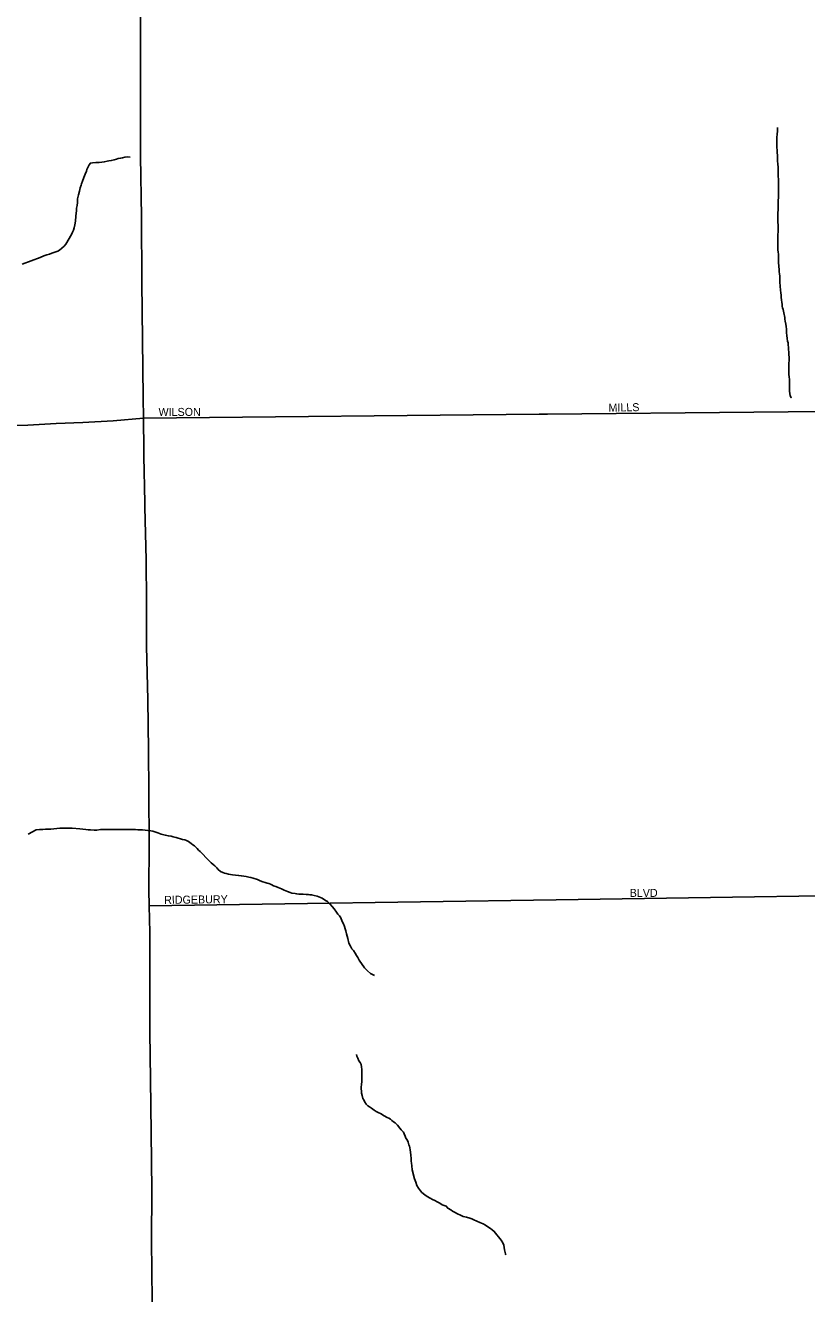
# Model space of a CAD drawing. Extents: x 2139079 to 2262683, y 1235796 to 1334992.
# Drawn here: x 2242458 to 2247339, y 1285350 to 1293274 of the extents above; entities that cross this region are included whole.
import ezdxf

# ---------------------------------------------------------------- set-up
doc = ezdxf.new("R2010")
doc.units = 0
for name, color, linetype in [('GM_X_City_Street', 7, 'Continuous'), ('GM_X_City_Street_Text', 7, 'Continuous'), ('GM_X_Minor_River', 7, 'Continuous'), ('GM_X_State_Route', 7, 'Continuous')]:
    doc.layers.add(name, color=color, linetype=linetype)

msp = doc.modelspace()

# ---------------------------------------------------------------- linework, layer by layer
at = {"layer": 'GM_X_City_Street'}
for points in [[(2245720.1, 1290844.7), (2248297.3, 1290870.7), (2252112.1, 1290916.7)], [(2240396.7, 1290746.9), (2240437.6, 1290747.3), (2241946, 1290761.4), (2242473.5, 1290775.7), (2242651.3, 1290787.6), (2242817.4, 1290793.7), (2243007, 1290803.3), (2243195.4, 1290819.4)], [(2243195.4, 1290819.4), (2245669.1, 1290844.2), (2245720.1, 1290844.7)], [(2243232, 1287772.5), (2245775.2, 1287810.6), (2245775.2, 1287810.6)], [(2245775.2, 1287810.6), (2248530.3, 1287852), (2249421.9, 1287863.7), (2249421.9, 1287863.7)]]:
    msp.add_lwpolyline(points, dxfattribs=at)
at = {"layer": 'GM_X_Minor_River'}
for points in [[(2247157.5, 1292635.4), (2247157.8, 1292615.3), (2247154, 1292593.2), (2247152.2, 1292575.2), (2247152.3, 1292565.1), (2247152.4, 1292555.1), (2247152.5, 1292545.1), (2247152.7, 1292529.1), (2247152.9, 1292511), (2247155.1, 1292495), (2247155.3, 1292478.9), (2247157.5, 1292462.9), (2247157.7, 1292442.8), (2247157.9, 1292426.8), (2247160.1, 1292408.8), (2247160.3, 1292386.7), (2247160.6, 1292366.7), (2247160.8, 1292346.6), (2247161, 1292330.6), (2247163.2, 1292312.5), (2247163.3, 1292298.5), (2247163.5, 1292286.5), (2247163.7, 1292268.4), (2247163.9, 1292250.4), (2247164.2, 1292222.3), (2247162.4, 1292200.2), (2247160.7, 1292178.1), (2247161, 1292152), (2247161.2, 1292126), (2247159.6, 1292097.9), (2247159.8, 1292073.8), (2247160.1, 1292047.7), (2247160.4, 1292023.7), (2247160.6, 1292003.6), (2247160.8, 1291987.6), (2247159.1, 1291963.5), (2247159.6, 1291911.3), (2247159.8, 1291897.3), (2247159.9, 1291885.3), (2247160.1, 1291871.2), (2247162.2, 1291857.2), (2247162.4, 1291845.2), (2247162.5, 1291833.1), (2247162.7, 1291819.1), (2247162.8, 1291807.1), (2247163, 1291789), (2247165.2, 1291773), (2247165.3, 1291763), (2247167.4, 1291753), (2247167.6, 1291734.9), (2247169.8, 1291720.9), (2247172, 1291706.9), (2247172.1, 1291690.8), (2247172.4, 1291668.8), (2247174.7, 1291644.7), (2247174.9, 1291620.7), (2247177.1, 1291602.6), (2247179.3, 1291588.6), (2247179.4, 1291574.6), (2247181.6, 1291558.6), (2247183.8, 1291542.5), (2247185.9, 1291532.5), (2247186.1, 1291520.5), (2247188.2, 1291508.5), (2247192.3, 1291498.5), (2247194.4, 1291488.5), (2247196.5, 1291478.5), (2247198.7, 1291468.5), (2247200.8, 1291458.5), (2247202.9, 1291448.5), (2247203, 1291438.4), (2247205.1, 1291426.4), (2247209.3, 1291408.4), (2247211.5, 1291392.4), (2247213.7, 1291376.4), (2247214, 1291354.3), (2247216.2, 1291336.3), (2247218.4, 1291318.3), (2247220.6, 1291302.2), (2247222.7, 1291290.2), (2247222.9, 1291276.2), (2247225, 1291264.2), (2247227.5, 1291218.1), (2247229.7, 1291200.1), (2247229.9, 1291182), (2247228.1, 1291161.9), (2247228.3, 1291145.9), (2247228.5, 1291131.8), (2247228.6, 1291117.8), (2247228.8, 1291107.8), (2247228.9, 1291093.7), (2247229.1, 1291077.7), (2247231.3, 1291061.7), (2247231.4, 1291049.6), (2247231.5, 1291039.6), (2247231.7, 1291021.6), (2247231.9, 1291003.5), (2247232.1, 1290989.5), (2247236.4, 1290959.4), (2247242.5, 1290949.5), (2247242.5, 1290949.5)], [(2242438.3, 1291781.6), (2242550.5, 1291823.1), (2242574.5, 1291833.4), (2242592.4, 1291839.6), (2242608.4, 1291845.8), (2242624.4, 1291852), (2242642.3, 1291858.2), (2242660.3, 1291864.4), (2242672.2, 1291870.6), (2242686.1, 1291882.7), (2242700, 1291894.9), (2242709.9, 1291907.1), (2242745.3, 1291967.6), (2242753.1, 1291981.8), (2242759, 1291993.9), (2242762.8, 1292009.9), (2242766.6, 1292028), (2242770.4, 1292050.1), (2242774, 1292082.3), (2242775.8, 1292100.3), (2242777.7, 1292116.4), (2242777.5, 1292132.5), (2242781.3, 1292148.6), (2242783.1, 1292166.6), (2242784.8, 1292190.7), (2242790.6, 1292214.8), (2242796.3, 1292239), (2242800.1, 1292259.1), (2242805.9, 1292275.2), (2242809.8, 1292285.2), (2242815.7, 1292301.4), (2242823.4, 1292323.5), (2242831.2, 1292343.6), (2242839, 1292363.8), (2242842.9, 1292373.9), (2242850.7, 1292390), (2242856.6, 1292402.1), (2242864.5, 1292414.2), (2242878.5, 1292416.4), (2242898.5, 1292416.6), (2242918.5, 1292416.8), (2242936.6, 1292419), (2242950.6, 1292421.2), (2242968.5, 1292425.4), (2242980.5, 1292427.5), (2242994.5, 1292429.7), (2243012.5, 1292433.9), (2243026.5, 1292438), (2243038.5, 1292442.2), (2243052.5, 1292444.3), (2243064.5, 1292446.5), (2243080.5, 1292450.7), (2243096.5, 1292452.8), (2243096.5, 1292452.8), (2243112.5, 1292451)], [(2247242.5, 1290949.5), (2247240.5, 1290949.4)], [(2242475.3, 1288221.8), (2242526.5, 1288248.8), (2242546.5, 1288249), (2242566.5, 1288249.2), (2242584.5, 1288251.4), (2242600.6, 1288251.6), (2242616.6, 1288251.8), (2242636.6, 1288254), (2242654.6, 1288256.2), (2242672.6, 1288258.4), (2242696.6, 1288258.6), (2242714.7, 1288258.8), (2242734.7, 1288259.1), (2242750.7, 1288259.2), (2242798.9, 1288253.7), (2242816.9, 1288251.9), (2242835, 1288250.1), (2242851, 1288248.3), (2242865.1, 1288248.4), (2242887.1, 1288246.7), (2242905.1, 1288246.8), (2242927.2, 1288249.1), (2242951.2, 1288249.4), (2242975.2, 1288249.6), (2242995.3, 1288249.8), (2243017.3, 1288250.1), (2243039.3, 1288250.3), (2243063.4, 1288250.6), (2243083.4, 1288250.8), (2243105.5, 1288249), (2243123.5, 1288249.2), (2243145.5, 1288249.5), (2243161.6, 1288247.6), (2243177.6, 1288247.8), (2243189.6, 1288247.9), (2243205.7, 1288246.1), (2243223.7, 1288244.3), (2243241.8, 1288242.5), (2243253.8, 1288238.6), (2243267.9, 1288234.8), (2243286, 1288228.9), (2243306.1, 1288221.1), (2243332.2, 1288215.4), (2243352.3, 1288209.6), (2243368.4, 1288207.8), (2243380.5, 1288203.9), (2243390.5, 1288202), (2243400.5, 1288200.1), (2243412.6, 1288196.2), (2243426.7, 1288192.4), (2243440.7, 1288188.5), (2243454.8, 1288184.6), (2243464.9, 1288180.7), (2243477, 1288174.8), (2243493.1, 1288163), (2243505.2, 1288155.1), (2243515.3, 1288147.2), (2243531.5, 1288131.3), (2243539.7, 1288121.4), (2243549.8, 1288111.5), (2243561.9, 1288099.6), (2243592.3, 1288069.8), (2243606.5, 1288053.9), (2243618.7, 1288042), (2243630.8, 1288032.1), (2243640.9, 1288022.2), (2243655.1, 1288010.3), (2243663.2, 1288000.4), (2243677.4, 1287988.5), (2243691.5, 1287980.6), (2243701.6, 1287976.7), (2243713.6, 1287974.8), (2243727.7, 1287971), (2243751.7, 1287967.2), (2243771.8, 1287965.4), (2243789.9, 1287963.6), (2243807.9, 1287959.8), (2243824, 1287958), (2243838, 1287956.1), (2243854.1, 1287952.3), (2243866.1, 1287950.4), (2243882.2, 1287946.6), (2243908.4, 1287936.8), (2243924.5, 1287929), (2243942.6, 1287923.2), (2243956.6, 1287919.3), (2243968.7, 1287915.4), (2243978.8, 1287911.6), (2243988.8, 1287907.6), (2243998.9, 1287903.8), (2244009, 1287897.8), (2244023, 1287894), (2244037.1, 1287888.1), (2244059.3, 1287880.3), (2244075.4, 1287870.5), (2244095.5, 1287862.7), (2244111.6, 1287856.8), (2244123.7, 1287853), (2244143.8, 1287849.2), (2244153.8, 1287847.3), (2244165.8, 1287845.4)], [(2244165.8, 1287845.4), (2244179.9, 1287845.6), (2244193.9, 1287845.7), (2244211.9, 1287843.9), (2244226, 1287844), (2244236, 1287842.1), (2244246, 1287842.2), (2244262.1, 1287838.4), (2244280.2, 1287832.6), (2244292.2, 1287828.7), (2244302.3, 1287824.8), (2244312.4, 1287820.9), (2244326.5, 1287811), (2244336.6, 1287805.1), (2244346.7, 1287799.2), (2244360.8, 1287785.3), (2244375.1, 1287769.4), (2244387.3, 1287753.5), (2244401.5, 1287733.6), (2244409.6, 1287721.7), (2244419.8, 1287709.8), (2244429.9, 1287697.8), (2244438.2, 1287675.9), (2244446.4, 1287659.9), (2244452.6, 1287643.9), (2244456.7, 1287629.9), (2244460.9, 1287615.9), (2244465.1, 1287597.9), (2244473.5, 1287567.9), (2244479.8, 1287539.9), (2244490, 1287522), (2244498.2, 1287504), (2244508.4, 1287494.1), (2244518.6, 1287478.2), (2244526.7, 1287462.2), (2244534.9, 1287450.3), (2244543.1, 1287434.3), (2244577.7, 1287386.6), (2244585.8, 1287376.6), (2244595.9, 1287366.7), (2244614.1, 1287350.9), (2244630.3, 1287341), (2244638.3, 1287337.1)], [(2244527.6, 1286844.5), (2244529.8, 1286834.5), (2244535.9, 1286820.5), (2244542.1, 1286804.6), (2244550.2, 1286794.6), (2244556.4, 1286782.7), (2244558.6, 1286766.6), (2244560.8, 1286750.6), (2244560.9, 1286738.6), (2244561.1, 1286722.5), (2244559.6, 1286678.4), (2244557.8, 1286654.3), (2244556, 1286642.3), (2244556.1, 1286632.2), (2244558.3, 1286612.2), (2244558.4, 1286602.2), (2244562.6, 1286588.2), (2244566.8, 1286570.2), (2244572.9, 1286560.2), (2244577, 1286550.2), (2244587.2, 1286534.3), (2244597.3, 1286524.4), (2244607.5, 1286516.5), (2244619.6, 1286508.6), (2244637.7, 1286496.7), (2244649.8, 1286488.8), (2244661.9, 1286481), (2244680.1, 1286473.1), (2244690.2, 1286467.2), (2244700.2, 1286461.3), (2244718.4, 1286451.5), (2244728.5, 1286445.6), (2244738.5, 1286439.7), (2244748.6, 1286431.8), (2244758.7, 1286423.8), (2244768.8, 1286417.9), (2244783, 1286402.1), (2244797.3, 1286384.2), (2244805.4, 1286374.2), (2244819.6, 1286358.3), (2244823.7, 1286348.3), (2244829.9, 1286334.4), (2244836, 1286322.4), (2244844.2, 1286310.5), (2244850.3, 1286296.5), (2244854.5, 1286280.5), (2244858.6, 1286270.5), (2244860.8, 1286260.5), (2244862.9, 1286248.5), (2244865, 1286234.5), (2244865.3, 1286214.4), (2244867.5, 1286194.4), (2244867.7, 1286178.3), (2244869.8, 1286164.3), (2244872, 1286148.3), (2244874.3, 1286124.3), (2244889, 1286066.3), (2244897.2, 1286046.3), (2244903.4, 1286026.3), (2244913.7, 1286008.4), (2244925.9, 1285992.5), (2244936, 1285982.6), (2244954.2, 1285966.7), (2244968.3, 1285956.8), (2244986.5, 1285947), (2245002.6, 1285939.1), (2245016.7, 1285931.3), (2245030.8, 1285923.4), (2245042.9, 1285917.5), (2245053, 1285911.6), (2245063.1, 1285905.7), (2245075.2, 1285899.8), (2245087.2, 1285895.9), (2245097.4, 1285884), (2245115.5, 1285874.2), (2245125.6, 1285866.3), (2245139.7, 1285858.4), (2245157.9, 1285848.6), (2245176, 1285840.8), (2245194.1, 1285832.9), (2245214.2, 1285827.1), (2245234.3, 1285821.3), (2245248.4, 1285817.5), (2245260.5, 1285811.6), (2245278.6, 1285803.8), (2245296.7, 1285793.9), (2245318.9, 1285786.1), (2245333, 1285778.3), (2245347.1, 1285768.4), (2245363.3, 1285756.6), (2245375.4, 1285748.6), (2245387.5, 1285738.8), (2245430.2, 1285683.1), (2245440.4, 1285667.1), (2245446.6, 1285653.2), (2245450.9, 1285623.1), (2245457.2, 1285599.1), (2245459.3, 1285593.1)]]:
    msp.add_lwpolyline(points, dxfattribs=at)
at = {"layer": 'GM_X_State_Route'}
for points in [[(2243177, 1293050.5), (2243177.1, 1293125.6), (2243177.6, 1293458.2), (2243176.9, 1293859), (2243174.9, 1294219.6), (2243173.9, 1294524.2), (2243171.1, 1294932.9), (2243169.4, 1295129.3), (2243168.2, 1295271.7)], [(2243198.8, 1290617.8), (2243195.4, 1290819.4), (2243193.2, 1290949.9), (2243189.3, 1291310.5), (2243185.3, 1291669.1), (2243182.6, 1292077.8), (2243178.3, 1292456.4), (2243176.7, 1292791), (2243176.9, 1292955.7), (2243177, 1293050.5)], [(2243202.3, 1290406.3), (2243201.2, 1290471.3), (2243199.2, 1290595.4), (2243198.8, 1290617.8)], [(2243255.6, 1284271.9), (2243255.2, 1284325.5), (2243253.9, 1284882.5), (2243250.9, 1285305.1), (2243246.7, 1285679.7), (2243247.5, 1285994.3), (2243243.5, 1286356.8), (2243240, 1286687.3), (2243235.1, 1286983.7), (2243235.9, 1287296.3), (2243234.8, 1287606.8), (2243232, 1287772.5), (2243230.4, 1287871.2), (2243231.6, 1288157.7), (2243230.2, 1288484.2), (2243227.8, 1288746.7), (2243222.6, 1289061.1), (2243215.1, 1289395.6), (2243214.5, 1289668), (2243212.1, 1289934.5), (2243204.7, 1290264.6), (2243204.5, 1290274.9), (2243202.3, 1290406.3)]]:
    msp.add_lwpolyline(points, dxfattribs=at)

# ---------------------------------------------------------------- texts
at = {"layer": 'GM_X_City_Street_Text'}
for s, rotation, p in [('WILSON', 0.00001, (2243290.1, 1290834.1)), ('MILLS', 1.10114, (2246101.5, 1290860.5)), ('BLVD', 0.00001, (2246233.7, 1287828.9)), ('RIDGEBURY', 0.70695, (2243325.2, 1287784.9))]:
    msp.add_text(s, height=50, rotation=rotation, dxfattribs=at).set_placement(p)

doc.saveas('drawing.dxf')
